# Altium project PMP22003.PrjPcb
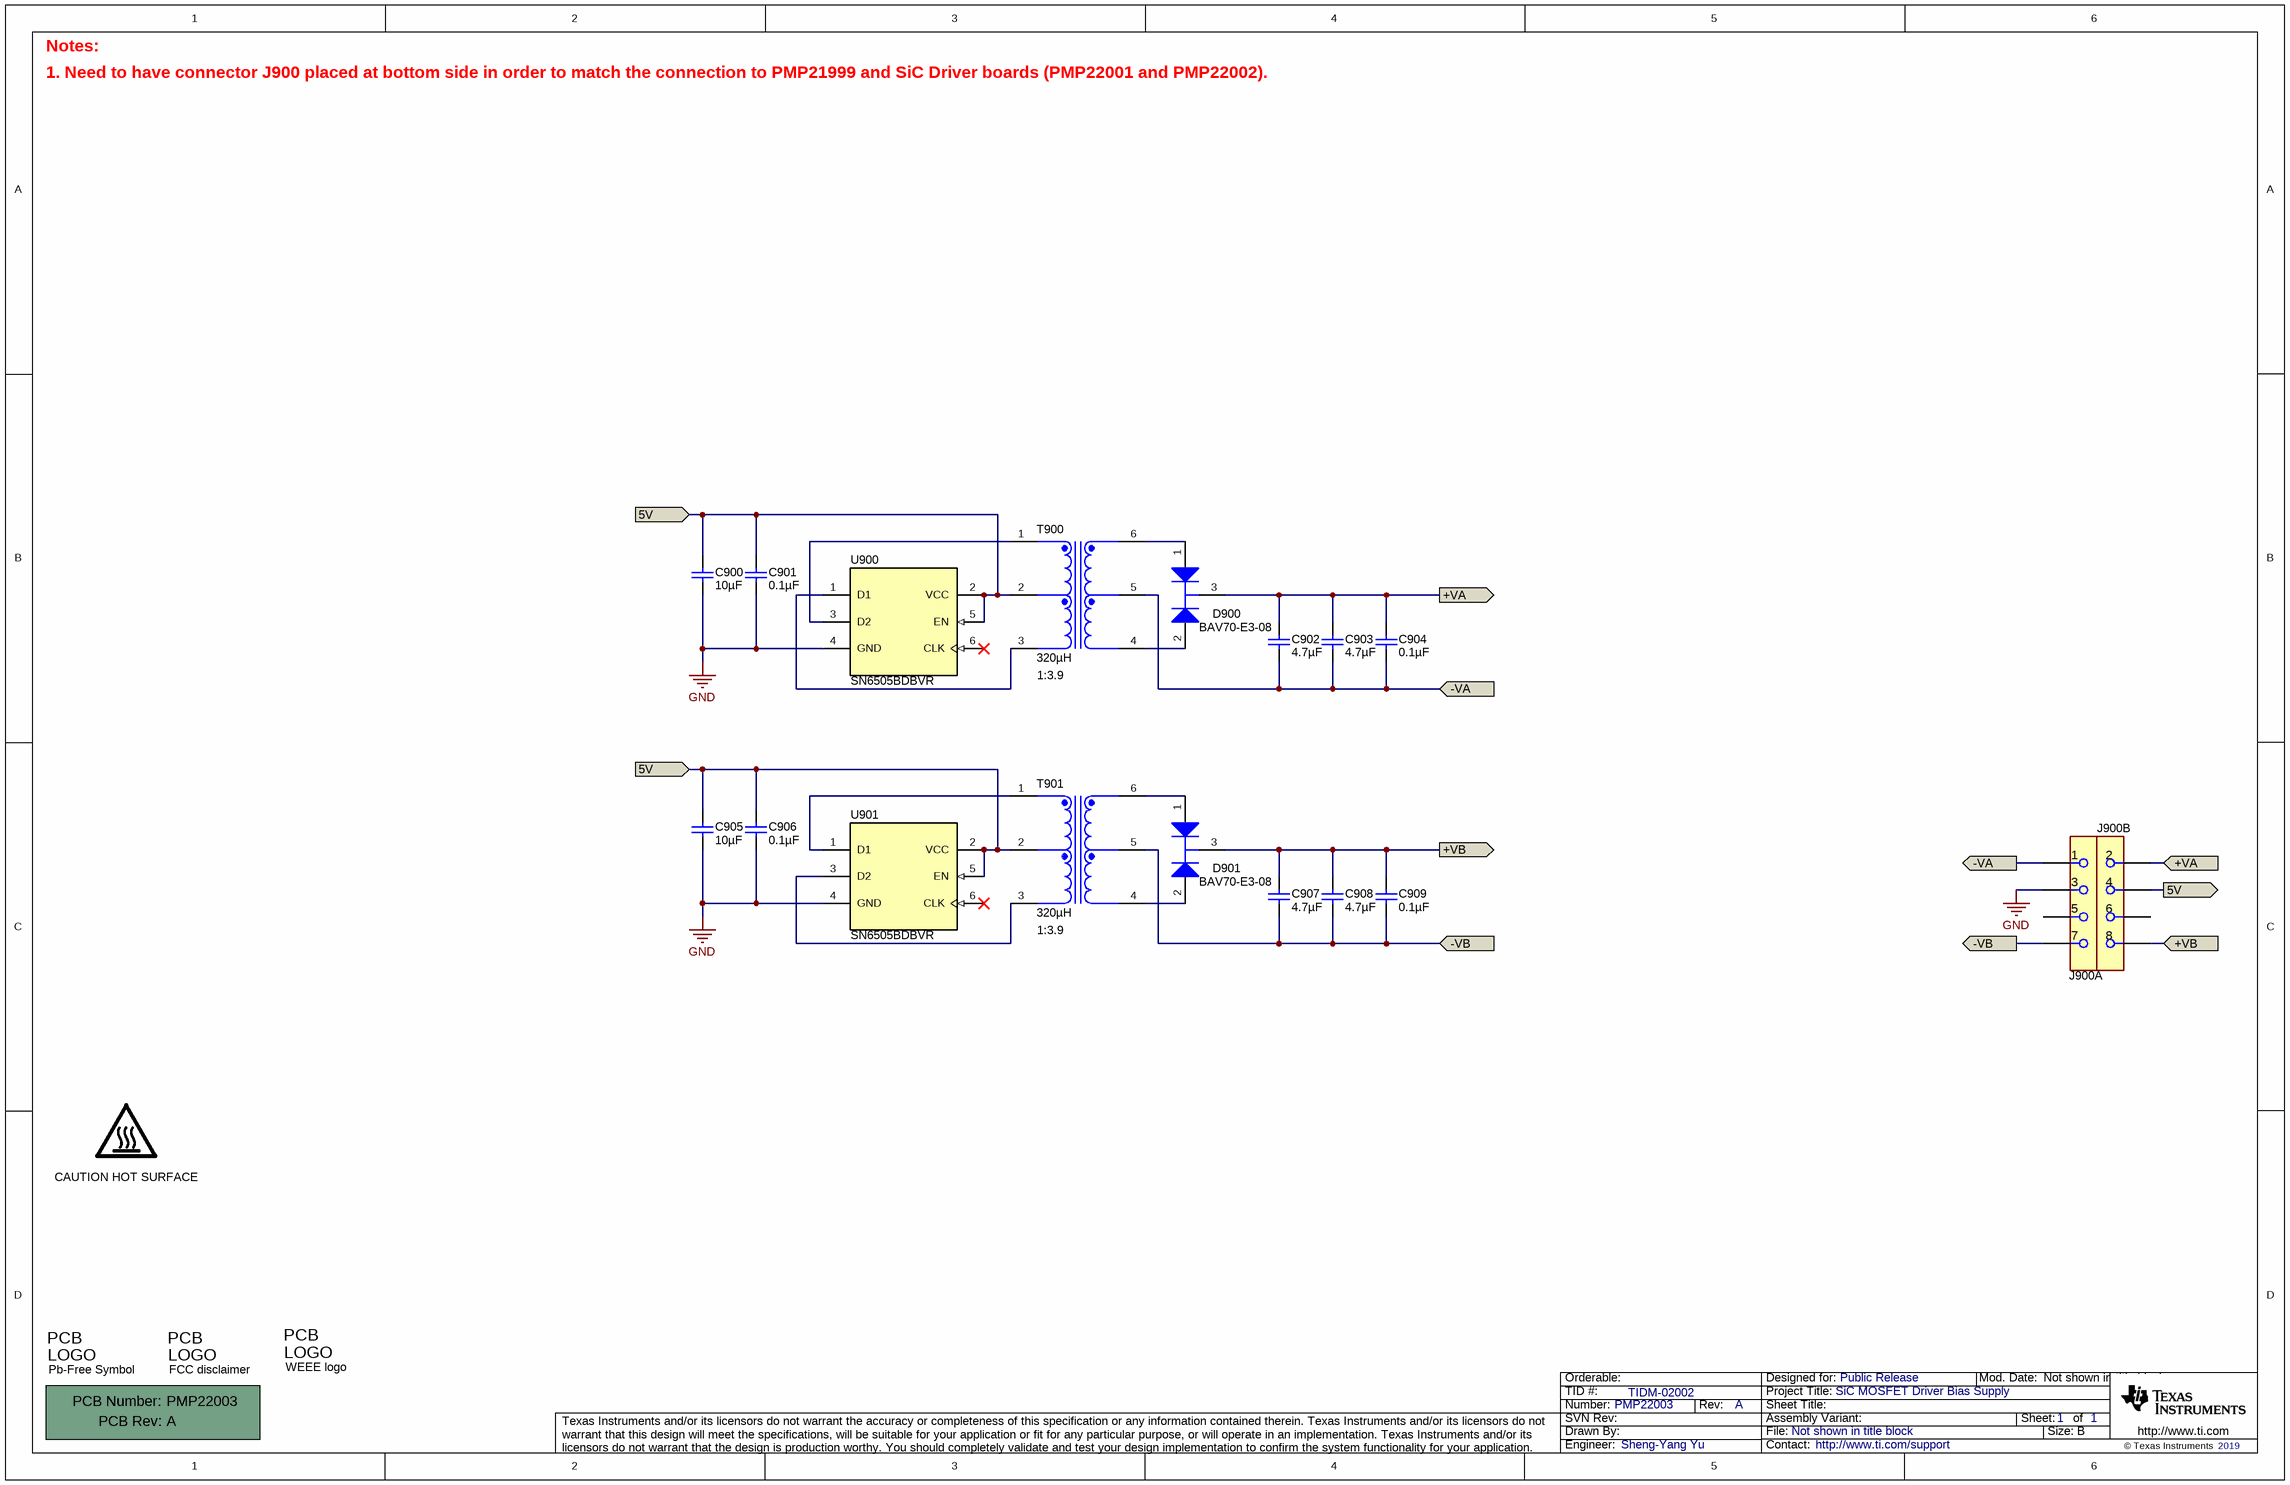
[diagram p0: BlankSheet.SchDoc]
CopyrightYear: 2019; PCB_Layout: Sheng-Yang Yu; PCB_Rev: A; PRJ_Customer: Public Release; PRJ_Engineer: Sheng-Yang Yu; PRJ_Number: PMP22003; PRJ_Title: SiC MOSFET Driver Bias Supply; SCH_Rev: A; TechSupport: http://www.ti.com/support; TID: TIDM-02002
1 sheet, 22 parts. Net scope: flat (ports and power ports of the same name join across sheets).
Board file: PCB.PcbDoc

## Sheet BlankSheet.SchDoc
size 431 x 279 mm; Date: Not shown in title block; ApprovedBy: Not shown in title block; CheckedBy: Not shown in title block; Author: Not shown in title block; CompanyName: Not shown in title block; Engineer: Not shown in title block; Organization: Not shown in title block; Address1: Not shown in title block; Address2: Not shown in title block; Address3: Not shown in title block; Address4: Not shown in title block; DocumentNumber: 1; Revision: Use project parameter SCH_Rev; SheetNumber: 1; SheetTotal: 1; PageSetup: Record=PageOptions¦CenterHorizontal=True¦CenterVertical=True¦PrintScale=1.00¦XCorrection=1.00¦YCorrection=1.00¦PrintKind=0¦BorderSize=5000000¦LeftOffset=0¦BottomOffset=0¦Orientation=2¦PaperLength=1000¦PaperWidth=1000¦Scale=100¦PaperSource=15¦PrintQuality=600¦MediaType=1¦DitherType=10¦PaperKind=Letter¦PrintScaleMode=1

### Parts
!PCB900  Printed Circuit Board  (value not drawn)  (mechanical)
C900  ValueDisplayed: 10µF  [0603]  (hidden comment: C1608X6S1A106M080AC)
C901  ValueDisplayed: 0.1µF  [0603]  (hidden comment: CGA3E2X7R1E104K080AA)
C902  ValueDisplayed: 4.7µF  [0805_HV]  (hidden comment: CGA4J3X5R1H475K125AB)
C903  ValueDisplayed: 4.7µF  [0805_HV]  (hidden comment: CGA4J3X5R1H475K125AB)
C904  ValueDisplayed: 0.1µF  [0603]  (hidden comment: CGA3E2X7R1E104K080AA)
C905  ValueDisplayed: 10µF  [0603]  (hidden comment: C1608X6S1A106M080AC)
C906  ValueDisplayed: 0.1µF  [0603]  (hidden comment: CGA3E2X7R1E104K080AA)
C907  ValueDisplayed: 4.7µF  [0805_HV]  (hidden comment: CGA4J3X5R1H475K125AB)
C908  ValueDisplayed: 4.7µF  [0805_HV]  (hidden comment: CGA4J3X5R1H475K125AB)
C909  ValueDisplayed: 0.1µF  [0603]  (hidden comment: CGA3E2X7R1E104K080AA)
D900  BAV70-E3-08  [SOT-23]
D901  BAV70-E3-08  [SOT-23]
J900  MMS-104-01-F-DH  [FP-MMS-104-01-F-DH_HDR8-MFG]  (value not drawn)  (parts A,B of 2)
LOGO900  CAUTION HOT SURFACE  [IEC_HotSurface_Small]  (no BOM)
Logo901  WEEE logo  [WEEE_Minimum]  (no BOM)
Logo902  Pb-Free Symbol  [Pb-Free_Overlay_Small]  (no BOM)
Logo903  FCC disclaimer  [FCC_disclaimer]  (no BOM)
T900  Ind_H: 320µH  [Wurth_750317722]  (hidden comment: 750317722)
T901  Ind_H: 320µH  [Wurth_750317722]  (hidden comment: 750317722)
U900  SN6505BDBVR  [DBV0006A_L]
U901  SN6505BDBVR  [DBV0006A_L]

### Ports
5V (in), 5V (out), +VA (in), +VA (out), +VB (in), +VB (out), -VA (in), -VA (out), -VB (in), -VB (out)

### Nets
GND: C900.2 C901.2 C905.2 C906.2 J900.3 U900.4(GND) U901.4(GND)
5V: C900.1 C901.1 C905.1 C906.1 J900.4 T900.2 T901.2 U900.2(VCC) U900.5(EN) U901.2(VCC) U901.5(EN) ; port 5V
+VA: C902.1 C903.1 C904.1 D900.3(C) J900.2 ; port +VA
+VB: C907.1 C908.1 C909.1 D901.3(C) J900.8 ; port +VB
-VA: C902.2 C903.2 C904.2 J900.1 T900.5 ; port -VA
-VB: C907.2 C908.2 C909.2 J900.7 T901.5 ; port -VB
NetD900_1: D900.1(A) T900.6
NetD900_2: D900.2(K) T900.4
NetD901_1: D901.1(A) T901.6
NetD901_2: D901.2(K) T901.4
NetT900_1: T900.1 U900.3(D2)
NetT900_3: T900.3 U900.1(D1)
NetT901_1: T901.1 U901.1(D1)
NetT901_3: T901.3 U901.3(D2)

Not connected (* = marked no-connect by the designer): J900 5 6; U900 6(CLK)*; U901 6(CLK)*

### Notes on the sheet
- Notes:
- 1. Need to have connector J900 placed at bottom side in order to match the connection to PMP21999 and SiC Driver boards (PMP22001 and PMP22002).
- (near T900) 1:3.9
- (near T901) 1:3.9

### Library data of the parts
!PCB900 = CMP-0003618-2: Manufacturer: Any; PartNumber: PMP22003
C900 C905 = GRT188C81A106ME13D: CAP, CERM, 10 µF, 10 V,+/- 20%, X6S, AEC-Q200 Grade 2, 0603; Manufacturer: TDK; Polarized: N; CompType: Capacitor; Value: 10uF; U/M: EA; Cap_F: 0.00001; Tolerance_%: 20; VDC_V: 10; Value2: 10V; TaMin_C: -55; TaMax_C: 105; SizeArea_mm2: 1.28; SizeAreaWB_mm2: 4.68; SizeX_mm: 1.6; SizeY_mm: 0.8; SizeZ_mm: 1; AEC Category: Q200; AEC Qualified: Y; AEC Grade: 2; Green_Lifecycle: Active; Green_REACh: Passed
C901 C904 C906 C909 = CGA3E2X7R1E104K080AA: CAP, CERM, 0.1 µF, 25 V,+/- 10%, X7R, AEC-Q200 Grade 1, 0603; Manufacturer: TDK; Polarized: N; CompType: Capacitor; Value: 0.1uF; U/M: EA; Cap_F: 0.0000001; Tolerance_%: 10; VDC_V: 25; Value2: 25V; TaMin_C: -55; TaMax_C: 125; SizeArea_mm2: 1.28; SizeAreaWB_mm2: 4.68; SizeX_mm: 1.6; SizeY_mm: 0.8; SizeZ_mm: 1; AEC Category: Q200; AEC Qualified: Y
C902 C903 C907 C908 = GRT21BR61H475KE13L: CAP, CERM, 4.7 µF, 50 V,+/- 10%, X5R, AEC-Q200 Grade 3, 0805; Manufacturer: TDK; Polarized: N; CompType: Capacitor; Value: 4.7uF; U/M: EA; Cap_F: 0.0000047; Tolerance_%: 10; VDC_V: 50; Value2: 50V; TaMin_C: -55; TaMax_C: 85; Cap_Case: 0805; SizeArea_mm2: 2.5; SizeAreaWB_mm2: 6.75; SizeX_mm: 2; SizeY_mm: 1.25; SizeZ_mm: 1.45; AEC Category: Q200; AEC Qualified: Y; AEC Grade: 3
D900 D901 = BAV70-E3-08: Diode, Switching, 70 V, 0.25 A, AEC-Q101, SOT-23; Manufacturer: Vishay-Semiconductor; SymbolCreator: a0412235; U/M: EA; Vf_V: 1.25; Value: 70V; Value1: 0.25A; Value2: 1.25V; Io_A: 0.25; Vr_V: 70; TJmax_C: 150; SizeAreaWB_mm2: 14; SizeArea_mm2: 7.5; SizeX_mm: 2.5; SizeY_mm: 3; SizeZ_mm: 1.1; AEC Category: Q101; AEC Qualified: Y; Green_Lifecycle: Not Set; Green_REACh: Incomplete
J900 = CMP-0087213-1: 8 Position Receptacle Connector Through Hole, Right Angle; Manufacturer: Samtec; Voltage_V: 350V; Row_Count: 2; Symbol Name: SYM-MMS-104-01-F-DH; ContactFinish: Gold,Nickel; Current_A: 3.9A
LOGO900 = IEC_HotSurface: IEC 61010-1 Hot Surface Warning; SymbolCreator: a0412235
Logo901 = CMP-0074769-1
Logo902 = CMP-0074839-1: SymbolCreator: a0412235; Library Reference: Logo
Logo903 = CMP-0074847-1: FCC_disclaimer; Library Reference: Logo
T900 T901 = CMP-0081994-1: Transformer, 320 uH, SMD; Manufacturer: Wurth Elektronik; SizeAreaWB_mm2: 108.7758; SizeArea_mm2: 70.3958; AEC Qualified: N; Lp: 320; AEC Category: Q200; SizeZ_mm: 4.19; SizeY_mm: 6.73; Ns1toNp: 4.18; Rsec1_ohm: 1.15; DCR_ohm: 0.4; SizeX_mm: 10.46
U900 U901 = CMP-0076095-1: Low-Noise 1 A, 420 kHz Transformer Driver, DBV0006A (SOT-23-6); Manufacturer: Texas Instruments; Alternate PartNumber: SN6505BDBVT; SizeAreaWB_mm2: 14.82; SizeArea_mm2: 8.12; SizeZ_mm: 1.45; Green_REACh: Passed; SizeY_mm: 2.9; Green_Lifecycle: Active; U/M: EA; CompType: IC; SizeX_mm: 2.8

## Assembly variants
001: all parts fitted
